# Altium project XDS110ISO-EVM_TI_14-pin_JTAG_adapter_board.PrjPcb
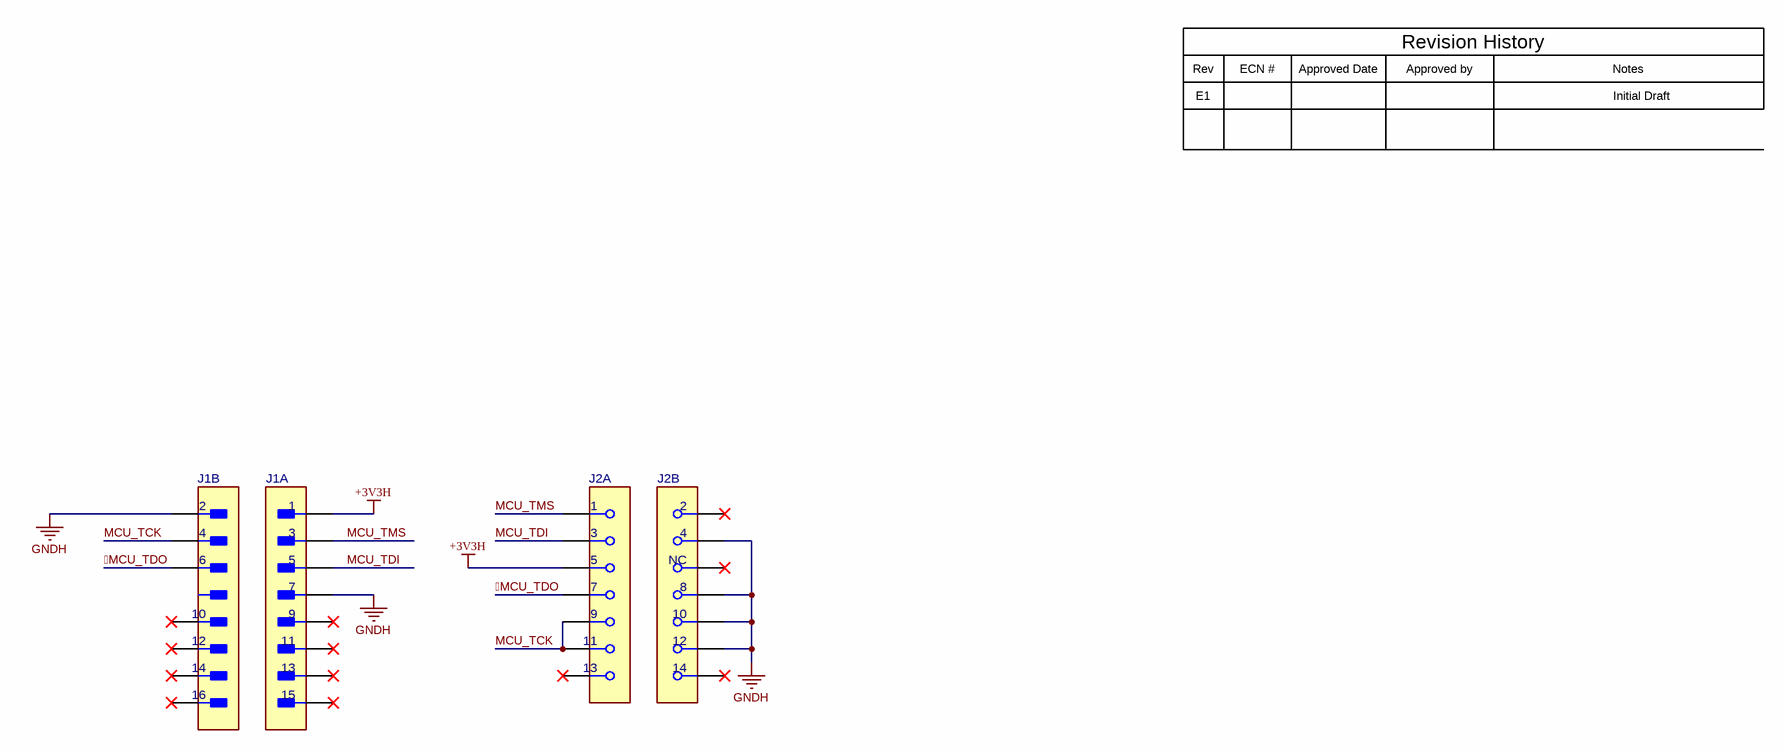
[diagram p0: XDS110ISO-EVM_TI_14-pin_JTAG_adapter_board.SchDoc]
TID: N/A; TechSupport: http://www.ti.com/support; SCH_Rev: A; PRJ_Number: XDS110ISO-EVM_TI_14-pin_JTAG_adapter_board; PRJ_Engineer: Sumit Patil; PRJ_Customer: XDS110ISO-EVM; PCB_Rev: A; PCB_Layout: Sumit Patil; Orderable: XDS110ISO-EVM_TI_14-pin_JTAG_adapter_board; DrawnBy: Sumit Patil; CopyrightYear: 2022
1 sheet, 2 parts. Net scope: global (net labels, ports and power ports of the same name join across sheets).
Board file: XDS110ISO-EVM_TI_14-pin_JTAG_adapter_board.PcbDoc

## Sheet XDS110ISO-EVM_TI_14-pin_JTAG_adapter_board.SchDoc
size 431 x 279 mm; Date: Not shown in title block; ApprovedBy: Not shown in title block; CheckedBy: Not shown in title block; Author: Not shown in title block; CompanyName: Not shown in title block; DrawnBy: Cody Watkins; Engineer: Not shown in title block; Organization: Not shown in title block; Address1: Not shown in title block; Address2: Not shown in title block; Address3: Not shown in title block; Address4: Not shown in title block; DocumentNumber: 1; Revision: Use project parameter SCH_Rev; SheetNumber: 1; SheetTotal: 8; PageSetup: Record=PageOptions¦CenterHorizontal=True¦CenterVertical=True¦PrintScale=1.00¦XCorrection=1.00¦YCorrection=1.00¦PrintKind=0¦BorderSize=5000000¦LeftOffset=0¦BottomOffset=0¦Orientation=2¦PaperLength=1000¦PaperWidth=1000¦Scale=100¦PaperSource=15¦PrintQuality=600¦MediaType=1¦DitherType=10¦PaperKind=Letter¦PrintScaleMode=1

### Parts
J1  TSM-108-01-L-DV-008-P-TR  [FP-TSM-108-01-L-DV-008-P-TR_HDR15-MFG]  (value not drawn)  (parts A,B of 2)
J2  SSW-107-22-G-D-VS-006  [FP-SSW-107-22-G-D-VS-006_HDR14-MFG]  (value not drawn)  (parts A,B of 2)

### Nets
+3V3H: J1.1 J2.5
GNDH: J1.2 J1.7 J2.4 J2.8 J2.10 J2.12
MCU_TDO: J1.6 J2.7
MCU_TCK: J1.4 J2.9 J2.11
MCU_TDI: J1.5 J2.3
MCU_TMS: J1.3 J2.1

Not connected (* = marked no-connect by the designer): J1 9* 10* 11* 12* 13* 14* 15* 16*; J2 2* 6(NC)* 13* 14*

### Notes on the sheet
- Rev
- E1
- ECN #
- Approved Date
- Approved by
- Revision History
- Notes
- Initial Draft

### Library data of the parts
J1 = CMP-0121706-1: Conn Unshrouded HDR 16 POS 2.54mm Solder ST SMT; Manufacturer: Samtec; ContactFinish: Gold,Nickel; Row_Count: 2; AEC Qualified: No; Conn Gender: Male; Conn Orientation: Vertical; SizeZ_mm: 10.16mm; Standoff Height: 1.02mm
J2 = CMP-0121832-1: 14 Position Receptacle Connector 0.100" (2.54mm) Surface Mount Gold; Manufacturer: Samtec; ContactFinish: Gold,Nickel; Current_A: 4.7A; Row_Count: 2; Voltage_V: 655V; AEC Qualified: No; Conn Gender: Female; Conn Orientation: Vertical; Is Female: yes; SizeZ_mm: 10.21mm

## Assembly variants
001: not fitted FID1 FID2 FID3 FID4 FID5 FID6 R17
